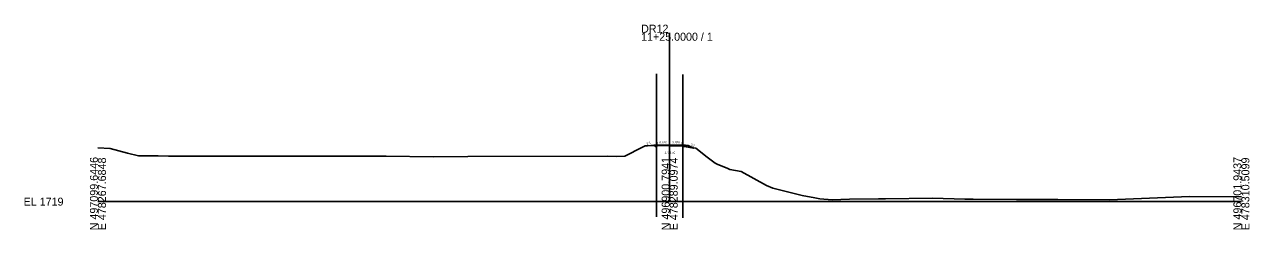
# Model space of a CAD drawing. Extents: x -26 to 403, y -10 to 3574.
# Drawn here: x -25.7 to 402.8, y 2490.3 to 2561.8 of the extents above; entities that cross this region are included whole.
import ezdxf

# ---------------------------------------------------------------- set-up
doc = ezdxf.new("R2010")
doc.units = 0
for name, color, linetype in [('Exist Cross Section Cell', 7, 'Continuous'), ('Exist XS Center Line Elevation Label', 7, 'Continuous'), ('Exist XS Ground Line', 7, 'Continuous'), ('Prop XS Ditch Slope Text', 7, 'Continuous'), ('Prop XS Earthwork Shape', 7, 'Continuous'), ('Prop XS EOT Tick Mark', 7, 'Continuous'), ('Prop XS Finish Grade', 7, 'Continuous'), ('Prop XS Finish Grade Earthwork', 7, 'Continuous'), ('Prop XS Finish Grade Pavement', 7, 'Continuous'), ('Prop XS Pvmt Edge Slope', 7, 'Continuous'), ('Prop XS SE Text', 7, 'Continuous'), ('Prop XS Shoulder Borrow Shape', 7, 'Continuous'), ('Prop XS Side Slope Text', 7, 'Continuous'), ('Prop XS Subgrade Earthwork', 7, 'Continuous'), ('Scratch_Level_1', 7, 'Continuous'), ('Scratch_Level_4', 7, 'Continuous'), ('Scratch_Level_6', 7, 'Continuous')]:
    doc.layers.add(name, color=color, linetype=linetype)

msp = doc.modelspace()

# ---------------------------------------------------------------- linework, layer by layer
at = {"layer": 'Exist Cross Section Cell'}
for p, q in [((200, 2500), (200, 2558.95)), ((0, 2500), (200, 2500)), ((200, 2500), (400, 2500))]:
    msp.add_line(p, q, dxfattribs=at)
at = {"layer": 'Exist XS Ground Line'}
msp.add_lwpolyline([(0, 2518.75), (4.26, 2518.53), (10.34, 2516.95), (14.13, 2516.02), (21.06, 2515.94), (24.65, 2515.91), (28.87, 2515.86), (51.55, 2515.91), (59.41, 2515.89), (78.25, 2515.92), (89.25, 2515.89), (100.87, 2515.9), (117.3, 2515.67), (129.44, 2515.74), (178.13, 2515.82), (181.5, 2515.78), (184.27, 2515.87), (190.45, 2518.97), (191.4, 2519.43), (192.2, 2519.48), (195.41, 2519.65), (200, 2519.5), (204.58, 2519.36), (209.14, 2518.61), (213.1, 2515.57), (215.96, 2513.42), (216.56, 2513.11), (220.35, 2511.52), (221.01, 2511.23), (224.98, 2510.53), (233.87, 2505.67), (236.13, 2504.68), (246.39, 2502.11), (250.8, 2501.3), (252.51, 2501), (256.84, 2500.58), (262.9, 2500.85), (273.06, 2500.93), (275.46, 2501.02), (291.92, 2501.18), (303.24, 2500.85), (306.23, 2500.84), (321.28, 2500.79), (335.84, 2500.73), (353.92, 2500.66), (381.84, 2501.78), (400, 2501.69)], dxfattribs=at)
at = {"layer": 'Prop XS Earthwork Shape'}
for points in [[(194.48, 2519.69), (193.5, 2519.61), (193.36, 2519.54), (194.56, 2519.61)], [(195.5, 2519.23), (194.95, 2519.22), (194.56, 2519.61), (195.41, 2519.65), (195.5, 2519.65)], [(204.58, 2519.36), (205.11, 2519.27), (205.05, 2519.22), (204.5, 2519.23), (204.5, 2519.36)], [(205.52, 2519.69), (206.5, 2519.61), (208.45, 2518.72), (205.11, 2519.27)]]:
    msp.add_lwpolyline(points, close=True, dxfattribs=at)
at = {"layer": 'Prop XS EOT Tick Mark'}
for p, q in [((195.5, 2519.77), (195.5, 2520.77)), ((204.5, 2519.77), (204.5, 2520.77))]:
    msp.add_line(p, q, dxfattribs=at)
at = {"layer": 'Prop XS Finish Grade'}
for p, q in [((195.5, 2519.77), (194.48, 2519.69)), ((204.5, 2519.77), (205.52, 2519.69))]:
    msp.add_line(p, q, dxfattribs=at)
at = {"layer": 'Prop XS Finish Grade Earthwork'}
for p, q in [((193.5, 2519.61), (193.36, 2519.54)), ((194.48, 2519.69), (193.5, 2519.61)), ((205.52, 2519.69), (206.5, 2519.61)), ((206.5, 2519.61), (208.45, 2518.72))]:
    msp.add_line(p, q, dxfattribs=at)
at = {"layer": 'Prop XS Finish Grade Pavement'}
for p, q in [((195.5, 2519.77), (200, 2519.86)), ((200, 2519.86), (204.5, 2519.77))]:
    msp.add_line(p, q, dxfattribs=at)
at = {"layer": 'Prop XS Pvmt Edge Slope'}
for p, q in [((195.5, 2519.77), (194.95, 2519.22)), ((204.5, 2519.77), (205.05, 2519.22))]:
    msp.add_line(p, q, dxfattribs=at)
at = {"layer": 'Prop XS Shoulder Borrow Shape'}
for points in [[(195.5, 2519.77), (194.48, 2519.69), (194.95, 2519.22)], [(204.5, 2519.77), (205.52, 2519.69), (205.05, 2519.22)]]:
    msp.add_lwpolyline(points, close=True, dxfattribs=at)
at = {"layer": 'Prop XS Subgrade Earthwork'}
for p, q in [((194.95, 2519.22), (194.48, 2519.69)), ((195.5, 2519.23), (194.95, 2519.22)), ((195.5, 2519.23), (195.5, 2519.65)), ((204.5, 2519.23), (204.5, 2519.36)), ((204.5, 2519.23), (205.05, 2519.22)), ((205.05, 2519.22), (205.52, 2519.69))]:
    msp.add_line(p, q, dxfattribs=at)
at = {"layer": 'Scratch_Level_1'}
for p, q in [((195.41, 2544.65), (195.41, 2494.65)), ((204.58, 2544.36), (204.58, 2494.36))]:
    msp.add_line(p, q, dxfattribs=at)
at = {"layer": 'Scratch_Level_4'}
msp.add_line((206.5, 2519.61), (208.45, 2518.72), dxfattribs=at)
msp.add_line((206.5, 2519.61), (208.45, 2518.72), dxfattribs=at)
msp.add_line((206.5, 2519.61), (208.45, 2518.72), dxfattribs=at)
at = {"layer": 'Scratch_Level_6'}
msp.add_line((195.5, 2519.65), (204.5, 2519.36), dxfattribs=at)

# ---------------------------------------------------------------- texts
at = {"layer": 'Exist Cross Section Cell'}
for s, p in [('11+25.0000 / 1', (190, 2556.15)), ('DR12', (190, 2558.95)), ('EL 1719', (-26, 2498.6))]:
    msp.add_text(s, height=2.8, dxfattribs=at).set_placement(p)
for s, p in [('N 497099.6446', (0, 2490)), ('E 478267.6848', (2.8, 2490)), ('N 496900.7941', (200, 2490)), ('E 478289.0974', (202.8, 2490)), ('N 496701.9437', (400, 2490)), ('E 478310.5099', (402.8, 2490))]:
    msp.add_text(s, height=2.8, rotation=90, dxfattribs=at).set_placement(p)
at = {"layer": 'Exist XS Center Line Elevation Label'}
msp.add_text('1738.50', height=0.75, dxfattribs=at).set_placement((198.22, 2516.75))
at = {"layer": 'Prop XS Ditch Slope Text'}
msp.add_text('2:1', height=0.75, rotation=26.5651, dxfattribs=at).set_placement((192.15, 2519.76))
at = {"layer": 'Prop XS SE Text'}
for rotation, p in [(1.1458, (196.46, 2520.29)), (358.8542, (200.96, 2520.34))]:
    msp.add_text('0.020', height=0.75, rotation=rotation, dxfattribs=at).set_placement(p)
at = {"layer": 'Prop XS Side Slope Text'}
msp.add_text('3:1', height=0.75, rotation=335.5456, dxfattribs=at).set_placement((207.3, 2519.7))

doc.saveas('drawing.dxf')
